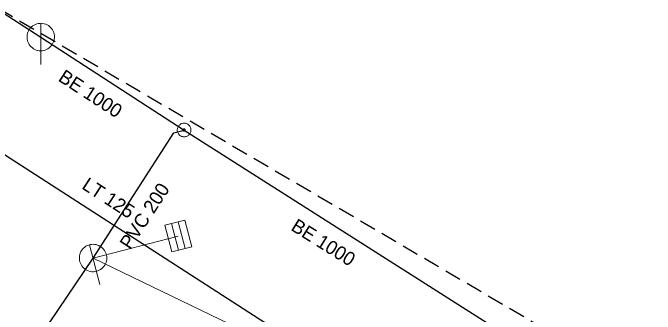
# Model space of a CAD drawing. Extents: x -791337 to -790755, y -988454 to -987923.
# Drawn here: x -791070.03 to -791023.23, y -988039.22 to -988017.27 of the extents above; entities that cross this region are included whole.
import ezdxf

# ---------------------------------------------------------------- set-up
doc = ezdxf.new("R2010")
doc.units = 0
doc.header["$LTSCALE"] = 0.4
doc.linetypes.add('MEDIUM_DASHED', pattern=[4.5, 3, -1.5])
for name, color, linetype, lineweight in [('1', 7, 'Continuous', 13), ('11', 7, 'Continuous', 13), ('14', 7, 'Continuous', 25), ('17', 7, 'Continuous', 25), ('22', 7, 'Continuous', 13), ('31', 7, 'Continuous', 13), ('63', 7, 'MEDIUM_DASHED', 25)]:
    doc.layers.add(name, color=color, linetype=linetype, lineweight=lineweight)

msp = doc.modelspace()

# ---------------------------------------------------------------- linework, layer by layer
at = {"layer": '11'}
for p in [(-791057.979, -988033.539), (-791047.079, -988043.389)]:
    msp.add_line(p, (-791064.19, -988035.129), dxfattribs=at)
at = {"layer": '14'}
for p, q in [((-791101.789, -987997.26), (-791068, -988019.03)), ((-791068, -988019.03), (-791057.554, -988025.804)), ((-791057.554, -988025.804), (-791034.09, -988040.71))]:
    msp.add_line(p, q, dxfattribs=at)
for points in [[(-791064.19, -988035.129), (-791058.306, -988026.002), (-791057.554, -988025.804)], [(-791080.519, -988059.839), (-791072.379, -988047.249), (-791064.19, -988035.129)]]:
    msp.add_lwpolyline(points, dxfattribs=at)
at = {"layer": '17'}
msp.add_lwpolyline([(-791043.809, -988044.929), (-791080.872, -988021.03), (-791082.371, -988020.047)], dxfattribs=at)
at = {"layer": '22'}
for p, q in [((-791068, -988021.03), (-791067.999, -988018.03)), ((-791057.981, -988032.495), (-791057.485, -988034.433)), ((-791058.465, -988032.619), (-791057.969, -988034.557)), ((-791063.693, -988037.066), (-791064.437, -988034.16))]:
    msp.add_line(p, q, dxfattribs=at)
for points in [[(-791067, -988019.03), (-791067.005, -988018.921), (-791067.023, -988018.813), (-791067.053, -988018.707), (-791067.093, -988018.606), (-791067.145, -988018.509), (-791067.207, -988018.419), (-791067.279, -988018.336), (-791067.359, -988018.262), (-791067.447, -988018.196), (-791067.541, -988018.141), (-791067.641, -988018.096), (-791067.746, -988018.063), (-791067.853, -988018.041), (-791067.962, -988018.031), (-791068.072, -988018.033), (-791068.18, -988018.047), (-791068.287, -988018.072), (-791068.39, -988018.109), (-791068.488, -988018.158), (-791068.58, -988018.216), (-791068.666, -988018.285), (-791068.743, -988018.362), (-791068.812, -988018.448), (-791068.871, -988018.54), (-791068.919, -988018.638), (-791068.956, -988018.741), (-791068.982, -988018.848), (-791068.996, -988018.956), (-791068.999, -988019.066), (-791068.989, -988019.175), (-791068.968, -988019.282), (-791068.934, -988019.386), (-791068.89, -988019.486), (-791068.835, -988019.581), (-791068.769, -988019.669), (-791068.695, -988019.749), (-791068.612, -988019.821), (-791068.522, -988019.883), (-791068.426, -988019.935), (-791068.324, -988019.976), (-791068.219, -988020.006), (-791068.111, -988020.024), (-791068.001, -988020.03), (-791067.892, -988020.024), (-791067.784, -988020.006), (-791067.679, -988019.977), (-791067.577, -988019.936), (-791067.48, -988019.884), (-791067.39, -988019.822), (-791067.307, -988019.751), (-791067.232, -988019.671), (-791067.167, -988019.583), (-791067.111, -988019.489), (-791067.067, -988019.389), (-791067.033, -988019.285), (-791067.011, -988019.177), (-791067.001, -988019.068)], [(-791057.496, -988032.371), (-791057, -988034.309), (-791058.453, -988034.681), (-791058.95, -988032.744)], [(-791063.221, -988034.881), (-791063.253, -988034.777), (-791063.298, -988034.677), (-791063.353, -988034.581), (-791063.417, -988034.494), (-791063.491, -988034.412), (-791063.574, -988034.341), (-791063.664, -988034.278), (-791063.76, -988034.226), (-791063.861, -988034.184), (-791063.966, -988034.154), (-791064.074, -988034.135), (-791064.184, -988034.129), (-791064.293, -988034.135), (-791064.401, -988034.152), (-791064.507, -988034.181), (-791064.609, -988034.222), (-791064.706, -988034.272), (-791064.797, -988034.334), (-791064.879, -988034.406), (-791064.954, -988034.485), (-791065.02, -988034.573), (-791065.076, -988034.666), (-791065.121, -988034.767), (-791065.156, -988034.871), (-791065.178, -988034.977), (-791065.188, -988035.086), (-791065.187, -988035.196), (-791065.174, -988035.305), (-791065.148, -988035.412), (-791065.112, -988035.515), (-791065.065, -988035.613), (-791065.006, -988035.706), (-791064.938, -988035.791), (-791064.862, -988035.87), (-791064.776, -988035.939), (-791064.684, -988035.998), (-791064.586, -988036.047), (-791064.483, -988036.085), (-791064.378, -988036.111), (-791064.269, -988036.126), (-791064.159, -988036.129), (-791064.05, -988036.119), (-791063.942, -988036.098), (-791063.838, -988036.065), (-791063.738, -988036.021), (-791063.644, -988035.967), (-791063.555, -988035.902), (-791063.474, -988035.827), (-791063.402, -988035.745), (-791063.339, -988035.656), (-791063.286, -988035.559), (-791063.245, -988035.458), (-791063.214, -988035.353), (-791063.196, -988035.245), (-791063.189, -988035.136), (-791063.195, -988035.026), (-791063.212, -988034.918)]]:
    msp.add_lwpolyline(points, close=True, dxfattribs=at)
at = {"layer": '31'}
for points in [[(-791057.134, -988026.076), (-791057.108, -988026.03), (-791057.087, -988025.982), (-791057.071, -988025.933), (-791057.06, -988025.882), (-791057.054, -988025.83), (-791057.055, -988025.777), (-791057.06, -988025.725), (-791057.071, -988025.674), (-791057.087, -988025.625), (-791057.108, -988025.576), (-791057.134, -988025.531), (-791057.166, -988025.489), (-791057.2, -988025.45), (-791057.239, -988025.415), (-791057.281, -988025.384), (-791057.327, -988025.358), (-791057.375, -988025.337), (-791057.425, -988025.321), (-791057.475, -988025.31), (-791057.527, -988025.304), (-791057.58, -988025.305), (-791057.633, -988025.31), (-791057.684, -988025.321), (-791057.733, -988025.336), (-791057.781, -988025.358), (-791057.826, -988025.384), (-791057.869, -988025.415), (-791057.907, -988025.45), (-791057.942, -988025.489), (-791057.973, -988025.531), (-791057.999, -988025.577), (-791058.02, -988025.625), (-791058.037, -988025.674), (-791058.047, -988025.725), (-791058.053, -988025.777), (-791058.053, -988025.83), (-791058.048, -988025.882), (-791058.037, -988025.933), (-791058.021, -988025.983), (-791057.999, -988026.031), (-791057.973, -988026.076), (-791057.943, -988026.118), (-791057.907, -988026.157), (-791057.868, -988026.192), (-791057.826, -988026.223), (-791057.78, -988026.249), (-791057.732, -988026.27), (-791057.683, -988026.287), (-791057.632, -988026.297), (-791057.58, -988026.303), (-791057.527, -988026.303), (-791057.476, -988026.297), (-791057.425, -988026.286), (-791057.375, -988026.27), (-791057.326, -988026.249), (-791057.281, -988026.223), (-791057.239, -988026.192), (-791057.2, -988026.157), (-791057.165, -988026.118)], [(-791057.485, -988025.848), (-791057.48, -988025.841), (-791057.477, -988025.833), (-791057.474, -988025.825), (-791057.473, -988025.817), (-791057.472, -988025.808), (-791057.472, -988025.799), (-791057.472, -988025.791), (-791057.474, -988025.782), (-791057.477, -988025.774), (-791057.48, -988025.766), (-791057.485, -988025.759), (-791057.49, -988025.752), (-791057.496, -988025.746), (-791057.501, -988025.74), (-791057.509, -988025.735), (-791057.516, -988025.73), (-791057.524, -988025.727), (-791057.532, -988025.724), (-791057.54, -988025.723), (-791057.549, -988025.722), (-791057.558, -988025.722), (-791057.566, -988025.722), (-791057.575, -988025.724), (-791057.584, -988025.727), (-791057.591, -988025.73), (-791057.598, -988025.735), (-791057.605, -988025.74), (-791057.611, -988025.746), (-791057.617, -988025.751), (-791057.622, -988025.759), (-791057.627, -988025.766), (-791057.63, -988025.774), (-791057.633, -988025.782), (-791057.634, -988025.79), (-791057.635, -988025.799), (-791057.636, -988025.807), (-791057.635, -988025.816), (-791057.633, -988025.825), (-791057.63, -988025.834), (-791057.627, -988025.841), (-791057.622, -988025.848), (-791057.617, -988025.855), (-791057.611, -988025.861), (-791057.606, -988025.867), (-791057.598, -988025.872), (-791057.591, -988025.877), (-791057.583, -988025.88), (-791057.575, -988025.883), (-791057.567, -988025.884), (-791057.558, -988025.885), (-791057.55, -988025.886), (-791057.541, -988025.885), (-791057.532, -988025.883), (-791057.524, -988025.88), (-791057.516, -988025.877), (-791057.509, -988025.872), (-791057.502, -988025.867), (-791057.496, -988025.861), (-791057.49, -988025.856)]]:
    msp.add_lwpolyline(points, close=True, dxfattribs=at)
at = {"layer": '63'}
msp.add_lwpolyline([(-791231.02, -987923.132), (-790755.118, -988202.253), (-790755.118, -988202.253), (-790903.053, -988400.429), (-790903.053, -988400.429), (-791331.504, -988073.857), (-791331.504, -988073.857)], close=True, dxfattribs=at)

# ---------------------------------------------------------------- texts
at = {"layer": '1'}
for s, rotation, p in [('BE 1000 ', 327, (-791066.793, -988022.178)), ('LT 125', 327, (-791065.076, -988030.033)), ('PVC 200 ', 57, (-791061.475, -988034.582)), ('BE 1000 ', 328, (-791049.84, -988033.056))]:
    msp.add_text(s, height=1, rotation=rotation, dxfattribs=at).set_placement(p)

doc.saveas('drawing.dxf')
